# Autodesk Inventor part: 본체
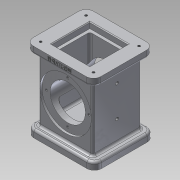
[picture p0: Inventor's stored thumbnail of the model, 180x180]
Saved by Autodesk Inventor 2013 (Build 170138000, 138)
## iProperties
Created: 2017-08
Part Number: 본체
Material: 알루미늄 6061
Document SubType Name: Modeling
Designer: Administrator
Density: 2.71 g/cm^3
Mass: 843.232 g
Surface Area: 643.489 cm^2
Volume: 311.156 cm^3
Author: Administrator
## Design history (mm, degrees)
sketch "스케치4"
  geometry: L1 (0, 0)-(-74, 0); L2 (-74, 0)-(-74, 88); L3 (-74, 88)-(0, 88); L4 (0, 88)-(0, 0)
  constraints: 8 end point, 2 parallel, 1 horizontal, 1 perpendicular
  dimensions: "d26" = 88 distance of L3.end L1.start; "d27" = 74 distance of L2.end L3.end
extrude "돌출1" new body sketch "스케치4" distance "d28" = 66; taper "d29" = 0 deg
sketch "스케치5"
  geometry: L1 (74, 0)-(0, 0) reference; L2 (74, 0)-(74, 66) reference; L3 (83, -8)-(-9, -8); L4 (-9, 74)-(83, 74); L5 (-9, 74)-(-9, -8); L6 (83, -8)-(83, 74)
  constraints: 8 end point, 1 parallel, 1 perpendicular
  dimensions: "d127" = 92 distance of L4.start L4.end; "d128" = 82 distance of L3.start L4.end; "d129" = 8 distance between parallel lines of L3 L1; "d130" = 9 distance between parallel lines of L6 L2
extrude "돌출2" join sketch "스케치5" distance "d31" = 10; taper "d32" = 0 deg
sketch "스케치6"
  geometry: L1 (0, 66)-(74, 66) reference; L2 (82, 74)-(82, -8); L3 (-10, -8)-(-10, 74); L4 (-10, 74)-(82, 74); L5 (-10, -8)-(82, -8)
  constraints: 8 end point, 1 parallel, 1 perpendicular
  dimensions: "d133" = 82 distance of L2.start L2.end; "d135" = 92 distance of L3.end L2.start; "d136" = 8 distance between parallel lines of L1 L4
extrude "돌출3" join sketch "스케치6" distance "d34" = 10; taper "d35" = 0 deg
fillet "모깎기1" dims "d36" = 3, "d53" = 10
sketch "스케치7"
  geometry: L1 (0, 88)-(0, 0) reference; L2 (1, 98)-(73, 98) reference; C1 r 35 at (37, 44)
  constraints: 1 centre point
  dimensions: "d37" = 37 distance from line of L1 C1.centre; "d38" = 54 distance from line of L2 C1.centre; "d39" = 70 diameter of C1
extrude "돌출4" cut sketch "스케치7" distance "d40" = 3; taper "d41" = 0 deg
sketch "스케치8"
  geometry: C1 r 35 at (37, -44) reference; C2 r 35 at (37, -44)
  constraints: 1 centre point, 1 coincident, 1 concentric
extrude "돌출5" cut sketch "스케치8" distance "d42" = 3; taper "d43" = 0 deg
sketch "스케치9"
  geometry: C1 r 35 at (0, 0) reference; C2 r 24 at (0, 0); 1 further point
  constraints: 1 centre point, 1 coincident
  dimensions: "d44" = 48 diameter of C2
extrude "돌출6" cut sketch "스케치9" stored distance "d46" = 3; taper "d47" = 0 deg
sketch "스케치10"
  geometry: L1 (73, 74)-(1, 74) reference; L2 (11, 59)-(63, 59); L3 (63, 59)-(63, 7); L4 (63, 7)-(11, 7); L5 (11, 7)-(11, 59); L6 (-9, 64)-(-9, 2) reference; 1 further point
  constraints: 8 end point, 2 parallel, 1 horizontal, 1 perpendicular
  dimensions: "d48" = 52 distance of L2.start L2.end; "d50" = 52 distance of L2.end L3.end; "d126" = 15 distance between parallel lines of L2 L1; "d131" = 20 distance between parallel lines of L6 L5
extrude "돌출7" cut sketch "스케치10" distance "d54" = 8; taper "d55" = 0 deg
sketch "스케치11"
  geometry: L1 (11, 59)-(63, 59) reference; L2 (11, 7)-(11, 59) reference; L3 (63, 7)-(11, 7) reference; L4 (63, 59)-(63, 7) reference; L5 (59, 55)-(15, 55); L6 (15, 55)-(15, 11); L7 (15, 11)-(59, 11); L8 (59, 11)-(59, 55); 1 further point
  constraints: 8 end point, 3 other
  dimensions: "d56" = 4 distance between parallel lines of L5 L1
extrude "돌출8" cut sketch "스케치11" distance "d57" = 74; taper "d58" = 0 deg
fillet "모깎기2" dims "d59" = 3
sketch "스케치12"
  geometry: 20 further points
  constraints: 4 coincident, 4 other
hole "구멍1" sketch "스케치12" at (1, 64), (73, 64), (73, 2), (1, 2) diameter "d60" = 3.242; stored, may be unused: countersink angle "d64" = 90 deg, drill point angle "d66" = 118 deg; dims "d61" = 4, "d62" = 4, "d63" = 2, "d65" = 6
sketch "스케치13"
  geometry: 20 further points
  constraints: 4 coincident, 4 other
hole "구멍2" sketch "스케치13" at (0, 64), (72, 64), (72, 2), (0, 2) diameter "d67" = 3.242; stored, may be unused: countersink angle "d71" = 90 deg, drill point angle "d73" = 118 deg; dims "d68" = 4, "d69" = 4, "d70" = 2, "d72" = 6
sketch "스케치14" dims "d74" = 58
  geometry: C1 r 24 at (0, 0) reference; C2 r 35 at (0, 0) reference; 3 further points
  constraints: 1 coincident, 1 vertical alignment, 2 other
  dimensions: "d76" = 0 horizontal distance of C1.centre point (0, 29)
hole "구멍3" sketch "스케치14" at (0, 29) diameter "d77" = 3.242; stored, may be unused: countersink angle "d81" = 90 deg, drill point angle "d83" = 118 deg; dims "d78" = 4, "d79" = 4, "d80" = 2, "d82" = 6
chamfer "모따기1" distance "d87" = 1; stored, may be unused: second distance "d88" = 2, angle "d89" = 45 deg
sketch "스케치15" dims "d90" = 58
  geometry: C1 r 24 at (0, 0) reference; C2 r 35 at (0, 0) reference; 3 further points
  constraints: 1 coincident, 1 vertical alignment, 2 other
  dimensions: "d92" = 0 horizontal distance of C1.centre point (0, -29)
hole "구멍4" sketch "스케치15" at (0, -29) diameter "d93" = 3.242; stored, may be unused: countersink angle "d97" = 90 deg, drill point angle "d99" = 118 deg; dims "d94" = 4, "d95" = 4, "d96" = 2, "d98" = 6
sketch "스케치16"
  geometry: L1 (88, 0)-(0, 0) reference; L2 (98, 64)-(98, 2) reference; 2 further points
  dimensions: "d100" = 33 distance from line of point (18, 33) L1; "d101" = 33 distance from line of L1 point (60, 33); "d102" = 38 distance from line of L2 point (60, 33); "d103" = 42 distance of point (60, 33) point (18, 33)
hole "구멍5" sketch "스케치16" at (18, 33), (60, 33) diameter "d104" = 4.134; stored, may be unused: countersink angle "d108" = 90 deg, drill point angle "d110" = 118 deg; dims "d105" = 4, "d106" = 4, "d107" = 2, "d109" = 20
sketch "스케치17"
  geometry: L1 (82, 2)-(82, 64) reference; L2 (60, 9)-(12, 9); L3 (12, 9)-(12, 57); L4 (12, 57)-(60, 57); L5 (60, 57)-(60, 9); L6 (0, -8)-(72, -8) reference
  constraints: 8 end point, 2 parallel, 1 horizontal, 1 perpendicular
  dimensions: "d111" = 48 distance of L2.start L2.end; "d113" = 48 distance of L2.end L3.end; "d115" = 22 distance between parallel lines of L5 L1; "d137" = 17 distance between parallel lines of L6 L2
extrude "돌출9" cut sketch "스케치17" distance "d116" = 16; taper "d117" = 0 deg
fillet "모깎기3" dims "d118" = 3
sketch "스케치18"
  geometry: L1 (0, 0)-(72, 0) reference; L2 (16.555, 0.528)-(55.445, 0.528); L3 (55.445, 0.528)-(55.445, -8.528); L4 (55.445, -8.528)-(16.555, -8.528); L5 (16.555, -8.528)-(16.555, 0.528); L6 (36, 0.528)-(36, -8.528); L7 (16.555, -4)-(55.445, -4); L8 (-10, 0)-(-10, -10) reference; 1 further point
  constraints: 4 end point, 4 midpoint, 2 other
  dimensions: "d120" = 4 distance between parallel lines of L7 L1; "d121" = 38.88974 distance of L2.start L2.end; "d122" = 9.05651 distance of L2.end L3.end; "d132" = 46 distance between parallel lines of L6 L8
feature "엠보싱1" sketch "스케치18" dims "d26" = 88, "d27" = 74, "d123" = 0.5, "d124" = 0
fillet "모깎기5" dims "d138" = 3
node "솔리드1"
pattern_circular "원형 패턴1" dims angle "d85" = 360 deg
pattern_circular "원형 패턴2" dims angle "d140" = 360 deg
node "투영된 루프1"
